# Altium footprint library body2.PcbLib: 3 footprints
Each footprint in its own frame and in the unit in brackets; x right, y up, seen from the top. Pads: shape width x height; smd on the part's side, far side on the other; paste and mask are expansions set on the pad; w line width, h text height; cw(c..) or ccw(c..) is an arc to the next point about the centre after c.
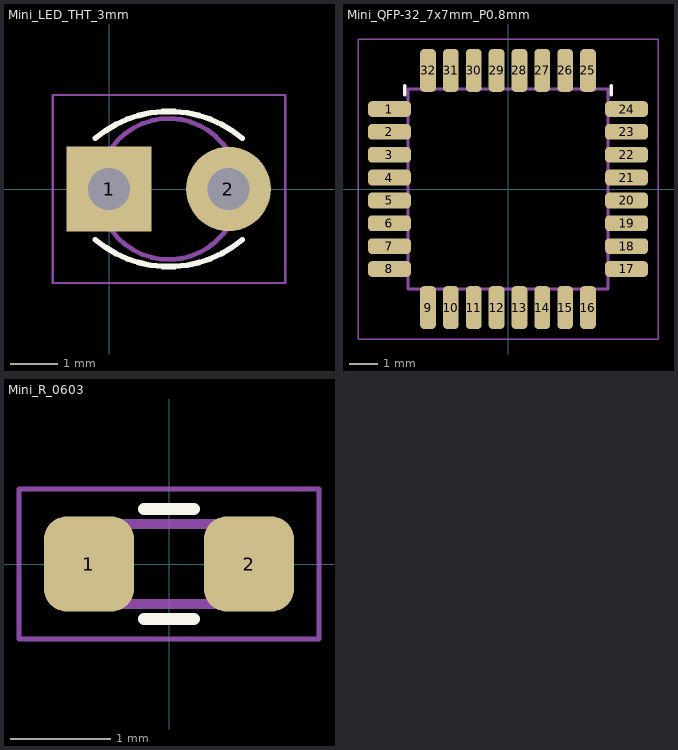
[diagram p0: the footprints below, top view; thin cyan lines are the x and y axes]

## Mini_LED_THT_3mm [mm] "Mini 3 mm through-hole LED. Synthetic geometry for Fenolite tests, not a validated land pattern"
pads (2):
  rect 1.8x1.8 hole 0.9: 1(0,0)
  round 1.8 hole 0.9: 2(2.54,0)
Top Overlay:
  lines w0.12: -0.29,-1.08 ccw(c1.27,0.77) 2.83,-1.08 ; -0.29,1.08 cw(c1.27,-0.77) 2.83,1.08
Mechanical 13:
  circle w0.1: c1.27,0 r1.5
Mechanical 15:
  lines w0.05: -1.2,-2 3.75,-2 3.75,2 -1.2,2 -1.2,-2

## Mini_QFP-32_7x7mm_P0.8mm [mm] "Mini QFP, 32 pins, 7 x 7 mm body, 0.8 mm pitch. Synthetic geometry for Fenolite tests, not a validated land pattern"
pads (32):
  rrect50% 1.5x0.55 smd: 1(-4.15,2.8) 2(-4.15,2) 3(-4.15,1.2) 4(-4.15,0.4) 5(-4.15,-0.4) 6(-4.15,-1.2) 7(-4.15,-2) 8(-4.15,-2.8) 17(4.15,-2.8) 18(4.15,-2) 19(4.15,-1.2) 20(4.15,-0.4) 21(4.15,0.4) 22(4.15,1.2) 23(4.15,2) 24(4.15,2.8)
  rrect50% 0.55x1.5 smd: 9(-2.8,-4.15) 10(-2,-4.15) 11(-1.2,-4.15) 12(-0.4,-4.15) 13(0.4,-4.15) 14(1.2,-4.15) 15(2,-4.15) 16(2.8,-4.15) 25(2.8,4.15) 26(2,4.15) 27(1.2,4.15) 28(0.4,4.15) 29(-0.4,4.15) 30(-1.2,4.15) 31(-2,4.15) 32(-2.8,4.15)
Top Overlay:
  lines w0.12: -3.61,3.3 -3.61,3.61 ; 3.61,3.3 3.61,3.61
Mechanical 13:
  lines w0.1: -3.5,-3.5 3.5,-3.5 3.5,3.5 -3.5,3.5 -3.5,-3.5
Mechanical 15:
  lines w0.05: -5.25,-5.25 -5.25,5.25 5.25,5.25 5.25,-5.25 -5.25,-5.25
3D body: height 2.5, standoff 0, extent -3.5,-3.5 3.5,3.5

## Mini_R_0603 [mm] "Mini 0603 resistor. Synthetic geometry for Fenolite tests, not a validated land pattern"
pads (2):
  rrect50% 0.9x0.95 smd: 1(-0.8,0) 2(0.8,0)
Top Overlay:
  lines w0.12: -0.25,-0.55 0.25,-0.55 ; -0.25,0.55 0.25,0.55
Mechanical 13:
  lines w0.1: -0.8,-0.4 0.8,-0.4 0.8,0.4 -0.8,0.4 -0.8,-0.4
Mechanical 15:
  lines w0.05: -1.5,-0.75 1.5,-0.75 1.5,0.75 -1.5,0.75 -1.5,-0.75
